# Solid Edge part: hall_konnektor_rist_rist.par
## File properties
Author: Romil
Template: iso part.par
Last saved by: Romil
Revision: 27
Application: Solid Edge
Accuracy: 0.990
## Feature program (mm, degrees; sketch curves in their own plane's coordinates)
sketch for "unnamed Protrusion 1" plane through (0, 0, 0) normal (1, 0, 0) x-axis (0, 1, 0)
  circle centre (0, 0) radius 3.35
extrude "unnamed Protrusion 1" add finite 16 symmetric
sketch for "ExtrudedCutout_1" plane through (0, 0, 0) normal (1, 0, 0) x-axis (0, 1, 0)
  circle centre (0, 0) radius 2.55
extrude "ExtrudedCutout_1" cut finite 26.4602 symmetric
sketch for "ExtrudedProtrusion_2" plane through (0, 0, 0) normal (1, 0, 0) x-axis (0, 1, 0)
  circle centre (0, 0) radius 2.85
extrude "ExtrudedProtrusion_2" add finite 1.56 symmetric
sketch for "ExtrudedCutout_2" plane through (0, 0, 0) normal (1, 0, 0) x-axis (0, 1, 0)
  circle centre (0, 0) radius 1.5
extrude "ExtrudedCutout_2" cut finite 517.645 symmetric
sketch for "unnamed Protrusion 2" plane through (-8, 0, 0) normal (-1, 0, 0) x-axis (0, -1, 0)
  line (-1.1715, -2.55) -> (1.1715, -2.55)
  line (1.2205, -2.55) -> (1.1715, -2.55)
  line (1.2763, -2.55) -> (1.2205, -2.55)
  line (0.6382, -1.9118) -> (1.2763, -2.55)
  line (-0.6382, -1.9118) -> (-1.2763, -2.55)
  line (-1.2763, -2.55) -> (-1.2205, -2.55)
  line (-1.2205, -2.55) -> (-1.1715, -2.55)
extrude "unnamed Protrusion 2" add to key point along -normal
mirror "unnamed Mirror 1" of "unnamed Protrusion 2" about plane through (0, 0, 0) normal (0, 0, 1)
extrude "unnamed Protrusion 3" add finite 16
sketch for "unnamed Protrusion 4" plane through (-8, 0, 0) normal (-1, 0, 0) x-axis (0, -1, 0)
  arc centre (-1.65, 0) radius 0.15 from (-1.5, 0) to (-1.65, 0.15) ccw
  line (-1.65, 0.15) -> (-3.1, 0.15)
  line (-3.1, 0.15) -> (-3.1, -0.15)
  line (-3.1, -0.15) -> (-1.65, -0.15)
  arc centre (-1.65, 0) radius 0.15 from (-1.65, -0.15) to (-1.5, 0) ccw
extrude "unnamed Protrusion 4" add to key point along -normal
mirror "unnamed Mirror 2" of "unnamed Protrusion 4" about plane through (0, 0, 0) normal (0, -1, 0)
extrude "unnamed Protrusion 5" add finite 16
sketch for "ExtrudedCutout_3" plane through (-8, 0, 0) normal (-1, 0, 0) x-axis (0, -1, 0)
  circle centre (3.9391, 3.9391) radius 2.45
extrude "ExtrudedCutout_3" cut finite 274.7271 symmetric
mirror "unnamed Mirror 3" of "ExtrudedCutout_3" about plane through (0, 0, 0) normal (0, -1, 0)
extrude "unnamed Cutout 1" cut finite 274.7271 symmetric
mirror "unnamed Mirror 4" of "ExtrudedCutout_3", "unnamed Mirror 3" about plane through (0, 0, 0) normal (0, 0, 1)
extrude "unnamed Cutout 2" cut finite 274.7271 symmetric
extrude "unnamed Cutout 3" cut finite 274.7271 symmetric
sketch for "ExtrudedCutout_7" plane through (-8, 0, 0) normal (-1, 0, 0) x-axis (0, -1, 0)
  line (-3.15, -3.7941) -> (-3.15, 4.9513)
  line (-3.15, 4.9513) -> (-5.3224, 4.9513)
  line (-5.3224, 4.9513) -> (-5.3224, -3.7941)
  line (-5.3224, -3.7941) -> (-3.15, -3.7941)
extrude "ExtrudedCutout_7" cut finite 49.4886 symmetric
mirror "unnamed Mirror 5" of "ExtrudedCutout_7" about plane through (0, 0, 0) normal (0, -1, 0)
extrude "unnamed Cutout 4" cut finite 49.4886 symmetric
fillet "Round_2" radius 0.5
sketch for "unnamed RevolvedProtrusion 1" plane through (0, 0, 0) normal (0, -1, 0) x-axis (1, 0, 0)
  line (0.086, 3.4049) -> (0.4761, 2.7468)
  line (0.4761, 2.7468) -> (0, 2.7468)
  line (-0.4761, 2.7468) -> (0, 2.7468)
  line (-0.086, 3.4049) -> (-0.4761, 2.7468)
  arc centre (0, 3.3539) radius 0.1 from (-0.086, 3.4049) to (0.086, 3.4049) cw
revolve "unnamed RevolvedProtrusion 1" add finite 360 deg
pattern "unnamed Pattern 1" of "unnamed RevolvedProtrusion 1"
revolve "unnamed RevolvedProtrusion 2" add finite 360 deg
revolve "unnamed RevolvedProtrusion 3" add finite 360 deg
sketch for "ExtrudedCutout_16" plane through (8, 0, 0) normal (1, 0, 0) x-axis (0, 0, -1)
  line (-3.512, -1.8908) -> (-1.8908, -3.512)
  arc centre (-3.2512, -3.1128) radius 1.4178 from (-2.0078, -2.4316) to (-1.8908, -3.512) cw
  arc centre (-3.9391, -3.9391) radius 2.45 from (-2.4316, -2.0078) to (-2.0078, -2.4316) cw
  arc centre (-3.1128, -3.2512) radius 1.4178 from (-2.4316, -2.0078) to (-3.512, -1.8908) ccw
extrude "ExtrudedCutout_16" cut finite 89.8858 symmetric
mirror "unnamed Mirror 6" of "ExtrudedCutout_16" about plane through (0, 0, 0) normal (0, 0, 1)
extrude "unnamed Cutout 5" cut finite 89.8858 symmetric
mirror "unnamed Mirror 7" of "ExtrudedCutout_16", "unnamed Mirror 6" about plane through (0, 0, 0) normal (0, -1, 0)
extrude "unnamed Cutout 6" cut finite 89.8858 symmetric
extrude "unnamed Cutout 7" cut finite 89.8858 symmetric
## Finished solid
Body 1: solid body, 183 faces, 536 edges, 356 vertices.
  Faces by surface: cylinder 117, plane 30, cone 24, torus 12
  Edges by curve: intersection 204, line 188, circle 144
Bounding box of the edges (mm; curved faces can reach further): 16.000 x 6.739 x 6.739, from (-8, -3.3697, -3.3697) to (8, 3.3697, 3.3697).
Cylindrical faces by radius (mm): R0.15 x4, R0.5 x48, R0.9025 x4, R1.4178 x24, R1.5 x1, R2.45 x4, R2.55 x8, R3.35 x24
Conical faces (half-angle, radius in mm at the cone's reference point): 59.3426 deg R2.7468 x12, 59.3426 deg R3.4049 x12
Toroidal faces (ring radius, tube radius in mm): R3.3539 r0.1 x12
Planar faces by outward normal: +x 3, +y 2, +z 2, -x 3, -y 2, -z 2, oblique 16
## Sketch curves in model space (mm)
arc centre (8, -3.1128, 3.2512) radius 1.4178 from (8, -2.4316, 2.0078) through (8, -2.9601, 1.8417) to (8, -3.512, 1.8908)
line (8, -1.8908, 3.512) -> (8, -3.512, 1.8908)
arc centre (8, -3.2512, 3.1128) radius 1.4178 from (8, -2.0078, 2.4316) through (8, -1.8417, 2.9601) to (8, -1.8908, 3.512)
arc centre (8, -3.9391, 3.9391) radius 2.45 from (8, -2.0078, 2.4316) through (8, -2.2067, 2.2067) to (8, -2.4316, 2.0078)
line (-1.2676, 0, 0) -> (3.2004, 0, 0)
line (0, 0, 3.55) -> (2.1726, 0, 3.55)
line (-0.4761, 0, 2.7468) -> (0, 0, 2.7468)
line (0.4761, 0, 2.7468) -> (0, 0, 2.7468)
line (0.086, 0, 3.4049) -> (0.4761, 0, 2.7468)
arc centre (0, 0, 3.3539) radius 0.1 from (-0.086, 0, 3.4049) through (0.003, 0, 3.4538) to (0.086, 0, 3.4049)
line (-0.086, 0, 3.4049) -> (-0.4761, 0, 2.7468)
circle centre (-8, -3.9391, 3.9391) radius 2.45
line (-8, 0, 0) -> (-8, -14.3473, 14.3473)
line (-8, 5.3224, 4.9513) -> (-8, 5.3224, -3.7941)
line (-8, 5.3224, -3.7941) -> (-8, 3.15, -3.7941)
line (-8, 3.15, -3.7941) -> (-8, 3.15, 4.9513)
line (-8, 3.15, 4.9513) -> (-8, 5.3224, 4.9513)
line (-8, 1.5, -0.15) -> (-8, 1.5, 0)
arc centre (-8, 1.65, 0) radius 0.15 from (-8, 1.65, -0.15) through (-8, 1.5409, -0.1029) to (-8, 1.5, 0)
arc centre (-8, 1.65, 0) radius 0.15 from (-8, 1.5, 0) through (-8, 1.5471, 0.1091) to (-8, 1.65, 0.15)
line (-8, 1.65, 0.15) -> (-8, 3.1, 0.15)
line (-8, 3.1, 0.15) -> (-8, 3.1, -0.15)
line (-8, 3.1, -0.15) -> (-8, 1.65, -0.15)
arc centre (-8, 1.6038, -1.1788) radius 1.3753 from (-8, 0.6313, -2.1513) through (-8, 0.6363, -2.1563) to (-8, 0.6414, -2.1613)
arc centre (-8, 0, -2.55) radius 0.75 from (-8, 0.6416, -2.1616) through (-8, 0.6415, -2.1615) to (-8, 0.6414, -2.1613)
line (-8, -1.2205, -2.55) -> (-8, -1.1715, -2.55)
line (-8, -1.2763, -2.55) -> (-8, -1.2205, -2.55)
line (-8, -0.6382, -1.9118) -> (-8, -1.2763, -2.55)
arc centre (-8, 0, -2.55) radius 0.9025 from (-8, 0.6382, -1.9118) through (-8, -0.0262, -1.6479) to (-8, -0.6382, -1.9118)
line (-8, 0.6382, -1.9118) -> (-8, 1.2763, -2.55)
line (-8, 1.2763, -2.55) -> (-8, 1.2205, -2.55)
line (-8, 1.2205, -2.55) -> (-8, 1.1715, -2.55)
line (-8, 1.1715, -2.55) -> (-8, -1.1715, -2.55)
circle centre (0, 0, 0) radius 1.5
circle centre (0, 0, 0) radius 2.85
circle centre (0, 0, 0) radius 3.35
circle centre (0, 0, 0) radius 2.55
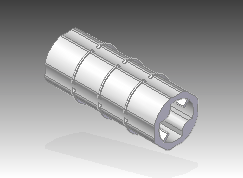
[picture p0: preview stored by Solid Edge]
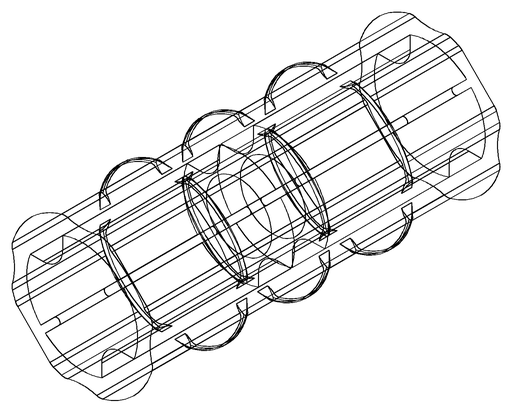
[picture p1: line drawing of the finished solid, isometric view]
